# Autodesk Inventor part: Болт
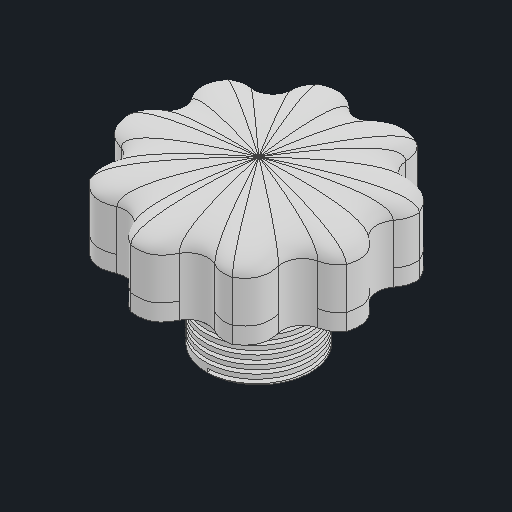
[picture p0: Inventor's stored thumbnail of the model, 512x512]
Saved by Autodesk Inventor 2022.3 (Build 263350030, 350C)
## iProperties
Created: 2020-09
Part Number: Болт
Material: Типовые
Document SubType Name: Modeling
Designer: Карташов
Density: 1 g/cm^3
Appearance: По умолчанию
Title: D:\мои документы\Ирина\_WorldSkills\2020_09 ФНЧ\Module A\GIVEN\Болт.stp
Author: Дом
Sending System: Autodesk Inventor 2021
Preprocessor: ST-DEVELOPER v18.1
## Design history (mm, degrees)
feature "Твердое тело2"
node "Твердое тело1"
